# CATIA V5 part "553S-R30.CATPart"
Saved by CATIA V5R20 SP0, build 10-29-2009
Part number: 553S-R30
Definition: NONE
Nomenclature: 553S-R30
Source: Unknown
Description: 553S-R30
Bounding box of the stored display mesh (mm): x -16.5 to 16.5, y -17.332 to 17.493, z -0.75 to 0.75
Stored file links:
  C:\Users\Utente\Desktop\IO LAVORO\3D X SITO CF\X SITO\PLASTICA\553S\553S-R30.CATPart
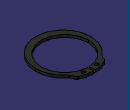
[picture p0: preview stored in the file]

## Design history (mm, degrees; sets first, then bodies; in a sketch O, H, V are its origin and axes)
Body1 "553S-R30" (main body)
  Solid1: solid without history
